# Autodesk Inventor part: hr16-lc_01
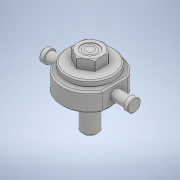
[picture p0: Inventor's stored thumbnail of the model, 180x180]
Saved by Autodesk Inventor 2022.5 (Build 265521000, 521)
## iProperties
Part Number: hr16-lc_01
Material: 一般
Document SubType Name: Modeling
Designer: ImaoCorp
Density: 1 g/cm^3
Appearance: 既定
Author: ImaoCorp
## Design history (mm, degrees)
feature "hr16-lc_01"
node "ソリッド1"
